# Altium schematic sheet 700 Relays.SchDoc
size Letter; Organization: Toradex Solutions Inc.; Address1: 6415 Northwest Drive; Address2: Mississauga, ON, L4V 1X1; Address3: Canada
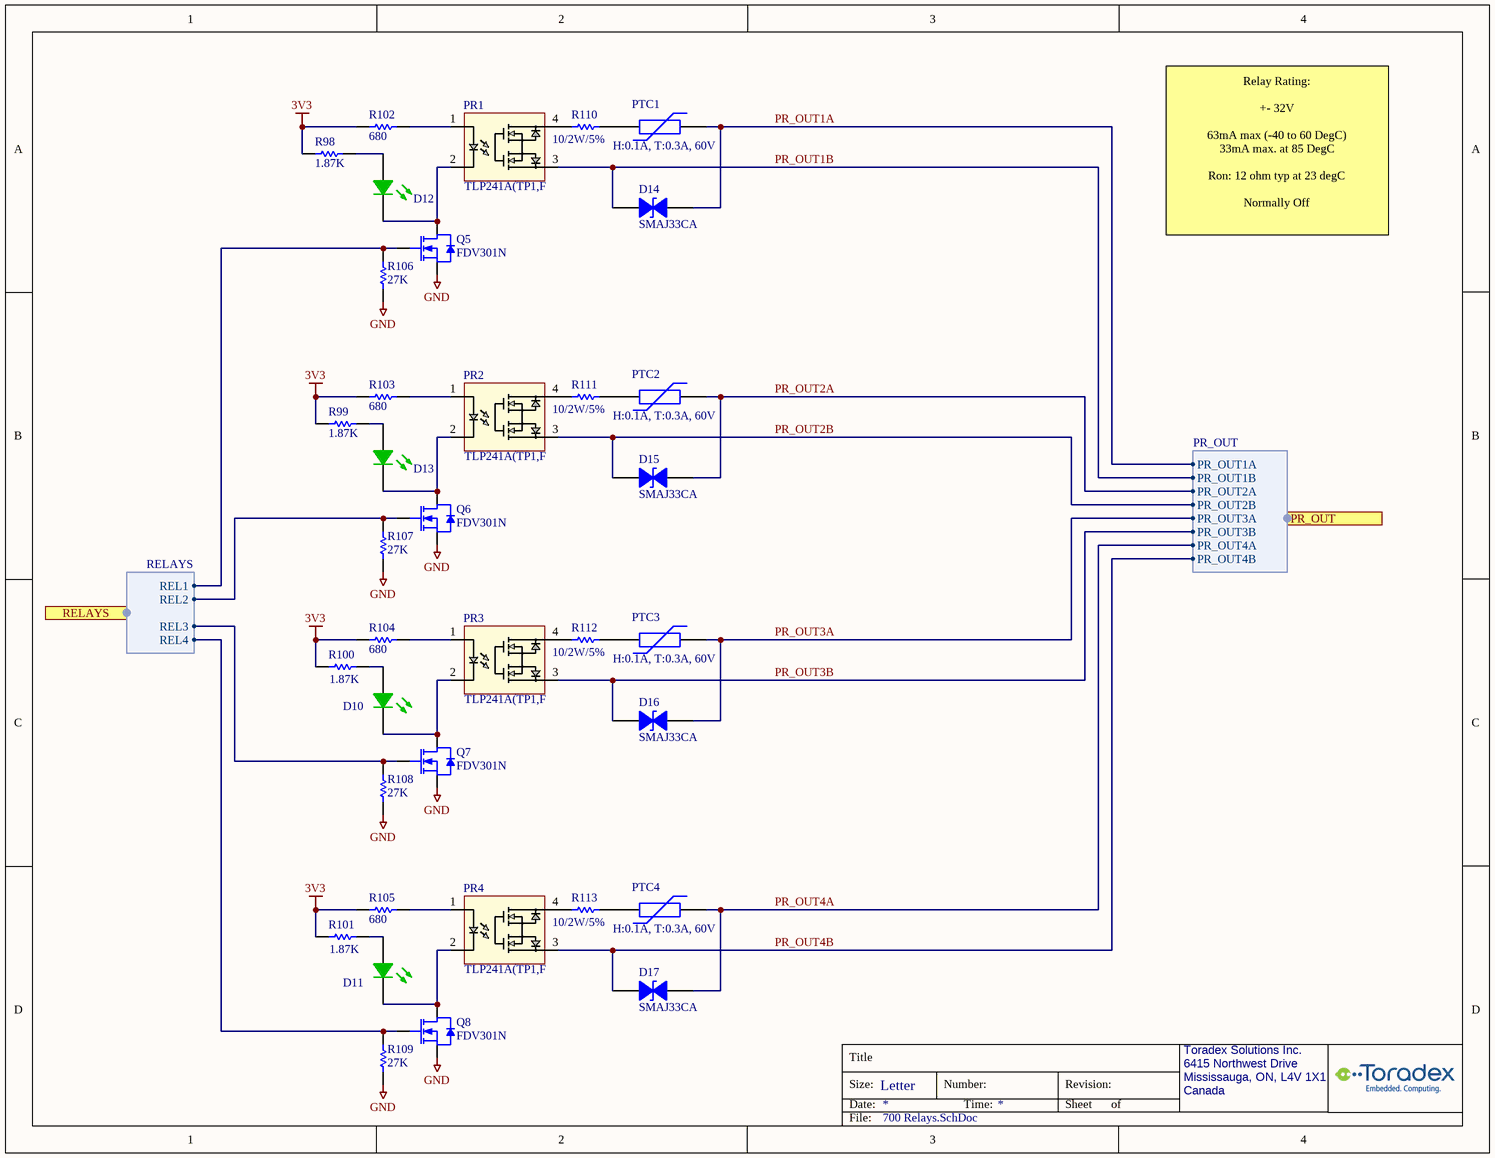
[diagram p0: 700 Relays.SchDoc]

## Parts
D10  Status  [LED-SMT-0603_APT1608CGCK]  (value not drawn)
D11  Status  [LED-SMT-0603_APT1608CGCK]  (value not drawn)
D12  Status  [LED-SMT-0603_APT1608CGCK]  (value not drawn)
D13  Status  [LED-SMT-0603_APT1608CGCK]  (value not drawn)
D14  SMAJ33CA  [SMAJ_TRANSIL]
D15  SMAJ33CA  [SMAJ_TRANSIL]
D16  SMAJ33CA  [SMAJ_TRANSIL]
D17  SMAJ33CA  [SMAJ_TRANSIL]
PR1  TLP241A  [TLP241A_TP1]  (value not drawn)
PR2  TLP241A  [TLP241A_TP1]  (value not drawn)
PR3  TLP241A  [TLP241A_TP1]  (value not drawn)
PR4  TLP241A  [TLP241A_TP1]  (value not drawn)
PTC1  H:0.1A, T:0.3A, 60V  [PTC_1812]
PTC2  H:0.1A, T:0.3A, 60V  [PTC_1812]
PTC3  H:0.1A, T:0.3A, 60V  [PTC_1812]
PTC4  H:0.1A, T:0.3A, 60V  [PTC_1812]
Q5  FDV301N  [SOT23]
Q6  FDV301N  [SOT23]
Q7  FDV301N  [SOT23]
Q8  FDV301N  [SOT23]
R98  value 1.87K  [R0402_RESC1005L]  (hidden comment: 1536-Res-0402-1.87K)
R99  value 1.87K  [R0402_RESC1005L]  (hidden comment: 1536-Res-0402-1.87K)
R100  value 1.87K  [R0402_RESC1005L]  (hidden comment: 1536-Res-0402-1.87K)
R101  value 1.87K  [R0402_RESC1005L]  (hidden comment: 1536-Res-0402-1.87K)
R102  value 680  [R/0603]  (hidden comment: 0864-Res-0603-680ohm)
R103  value 680  [R/0603]  (hidden comment: 0864-Res-0603-680ohm)
R104  value 680  [R/0603]  (hidden comment: 0864-Res-0603-680ohm)
R105  value 680  [R/0603]  (hidden comment: 0864-Res-0603-680ohm)
R106  value 27K  [R0402_RESC1005L]  (hidden comment: 1538-Res-0402-27k)
R107  value 27K  [R0402_RESC1005L]  (hidden comment: 1538-Res-0402-27k)
R108  value 27K  [R0402_RESC1005L]  (hidden comment: 1538-Res-0402-27k)
R109  value 27K  [R0402_RESC1005L]  (hidden comment: 1538-Res-0402-27k)
R110  value 10/2W/5%  [R/2512]  (hidden comment: 1424-Res-2512-10ohm-5%-2W)
R111  value 10/2W/5%  [R/2512]  (hidden comment: 1424-Res-2512-10ohm-5%-2W)
R112  value 10/2W/5%  [R/2512]  (hidden comment: 1424-Res-2512-10ohm-5%-2W)
R113  value 10/2W/5%  [R/2512]  (hidden comment: 1424-Res-2512-10ohm-5%-2W)

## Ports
PR_OUT (harness PR_OUT), RELAYS (harness RELAYS)

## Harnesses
RELAYS: REL1, REL2, REL3, REL4
PR_OUT: PR_OUT1A, PR_OUT1B, PR_OUT2A, PR_OUT2B, PR_OUT3A, PR_OUT3B, PR_OUT4A, PR_OUT4B

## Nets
3V3: R98.1 R99.1 R100.1 R101.1 R102.1 R103.1 R104.1 R105.1
GND: Q5.2(S) Q6.2(S) Q7.2(S) Q8.2(S) R106.1 R107.1 R108.1 R109.1
PR_OUT1A: D14.2 PTC1.2 ; port PR_OUT.PR_OUT1A
PR_OUT1B: D14.1 PR1.3 ; port PR_OUT.PR_OUT1B
PR_OUT2A: D15.2 PTC2.2 ; port PR_OUT.PR_OUT2A
PR_OUT2B: D15.1 PR2.3 ; port PR_OUT.PR_OUT2B
PR_OUT3A: D16.2 PTC3.2 ; port PR_OUT.PR_OUT3A
PR_OUT3B: D16.1 PR3.3 ; port PR_OUT.PR_OUT3B
PR_OUT4A: D17.2 PTC4.2 ; port PR_OUT.PR_OUT4A
PR_OUT4B: D17.1 PR4.3 ; port PR_OUT.PR_OUT4B
NetD10_1: D10.1(A) R100.2
NetD10_2: D10.2(K) PR3.2 Q7.3(D)
NetD11_1: D11.1(A) R101.2
NetD11_2: D11.2(K) PR4.2 Q8.3(D)
NetD12_1: D12.1(A) R98.2
NetD12_2: D12.2(K) PR1.2 Q5.3(D)
NetD13_1: D13.1(A) R99.2
NetD13_2: D13.2(K) PR2.2 Q6.3(D)
NetPR1_1: PR1.1 R102.2
NetPR1_4: PR1.4 R110.2
NetPR2_1: PR2.1 R103.2
NetPR2_4: PR2.4 R111.2
NetPR3_1: PR3.1 R104.2
NetPR3_4: PR3.4 R112.2
NetPR4_1: PR4.1 R105.2
NetPR4_4: PR4.4 R113.2
NetPTC1_1: PTC1.1 R110.1
NetPTC2_1: PTC2.1 R111.1
NetPTC3_1: PTC3.1 R112.1
NetPTC4_1: PTC4.1 R113.1
NetQ5_1: Q5.1(G) R106.2 ; port RELAYS.REL1
NetQ6_1: Q6.1(G) R107.2 ; port RELAYS.REL2
NetQ7_1: Q7.1(G) R108.2 ; port RELAYS.REL3
NetQ8_1: Q8.1(G) R109.2 ; port RELAYS.REL4

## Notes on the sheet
- Relay Rating:
  +- 32V
  63mA max (-40 to 60 DegC)
  33mA max. at 85 DegC
  Ron: 12 ohm typ at 23 degC
  Normally Off

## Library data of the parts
D10-D13 = 0333-LED Green 0603: (-40 to 85 DegC) LED GREEN 0603 50mcd; MfrNo: APT1608CGCK; Mfr: Kingbright; Alt: 754-1357-1-ND; Alt2: 160-1834-1-ND; PN: 333; DR: 754-1116-6-ND; DR2: 604-APT1608CGCK
D14-D17 = 0581-SMAJ33CA: (-55 to 150 DegC) TVS DIODE 33VWM Vbrm:36.7V Vcl:53.3V 400W SMA; MfrNo: SMAJ33CA-E3/5A; Mfr: Vishay Semiconductor Diodes Division; PN: 581; Desc: (-55 to 150 DegC) TVS DIODE 33VWM Vbrm:36.7V Vstd:53.3VC SMA; Alt: SMAJ33CA-E3/61GICT-ND; Alt2: SMAJ33CABCT-ND; DR: SMAJ33CA-E3/5AGIDKR-ND; DR2: 625-SMAJ33CA-E3/5A
PR1-PR4 = 1078-PhotoRelay-TLP241A: (-40 to 85 DegC) SSR RELAY SPST-NO 2A 0-40V 90mOhm typ 5x12.5mm; Mfr: Toshiba; MfrNo: TLP241A(TP1,F; PN: 1078
PTC1-PTC4 = 1423-PTC-0.1A-60V-1812: (-40 to 85 DegC) PTC Ih:0.1A, It:0.3A, 60V, 1812, 1.6-15ohm; MfrNo: 0ZCG0010FF2C; Mfr: Bel; PN: 1423; Alt: MPTS1812L010R,MPTS1812L010,1812L010/60DR,PTSA181260V010,MF-MSMF010-2,PFMF.010.2,MINISMDC010F-2,MINIASMDC010F-2
Q5-Q8 = 0761-FDV301N: (-55 to 155 DegC) MOSFET N-CH 25V 220MA SOT-23 Vth:1.1V Ron typ:4ohm@3V Vgsm:8V; Mfr: Fairchild/ON Semiconductor; PN: 761; DR: FDV301NDKR-ND; TR: FDV301NTR-ND; Alt: DMN62D0U-13, DMN62D0U-7, DMN61D9U-7
R98-R101 = 1536-Res-0402-1.87K: (-55 to 155 DegC AEC) RES 1.87K OHM 1% 1/16W 100ppm 0402; MfrNo: RMCF0402FT1K87; Mfr: Stackpole Electronics; Alt: AC0402FR-071K87L,RK73H1ETTP1871F,ERJ-2RKF1871X; PN: 1536
R102-R105 = 0864-Res-0603-680ohm: RES SMD 680 OHM 1% 1/10W 0603; Mfr: Yageo; MfrNo: RC0603FR-07680RL; Alt: RMCF0603FT680R; PN: 864; Alt2: AC0603FR-07680RL
R106-R109 = 1538-Res-0402-27k: (-55 to 155 DegC AEC) RES 27K OHM 1% 1/16W 100ppm 0402; Mfr: Stackpole Electronics; MfrNo: RMCF0402FT27K0; PN: 1538; Alt: AC0402FR-0727KL,CRGCQ0402F27K
R110-R113 = 1424-Res-2512-10ohm-5%-2W: (-55 to 155 DegC) RES SMD 10 OHM 5% 2W Pulse 2512; MfrNo: CRM2512AJW-100ELF; Mfr: Bourns; PN: 1424; Alt: CRS2512-JX-100ELF,CRM2512AFX-10R0ELF,SR2512JK-7W10RL,SR2512FK-7W10RL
